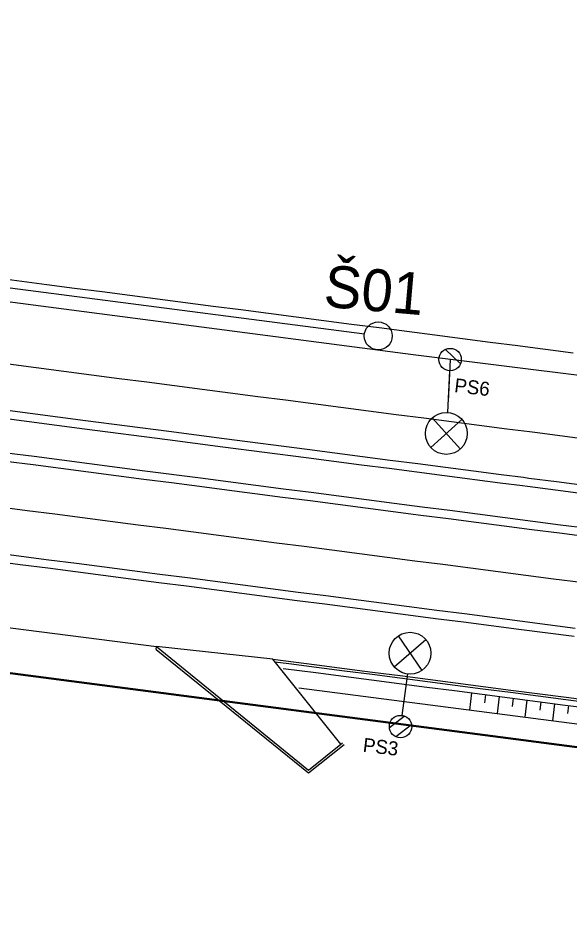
# Model space of a CAD drawing. Extents: x -669661 to -669105, y -977202 to -977030.
# Drawn here: x -669176.021 to -669175.034, y -977098.402 to -977096.811 of the extents above; entities that cross this region are included whole.
import ezdxf

# ---------------------------------------------------------------- set-up
doc = ezdxf.new("R2010")
doc.units = 0
doc.layers.add('Schéma', color=7, linetype='Continuous')

msp = doc.modelspace()

# ---------------------------------------------------------------- linework, layer by layer
at = {"layer": 'Schéma'}
for p, q in [((-669175.313, -977097.4136), (-669176.4676, -977097.2634)), ((-669175.2549, -977097.4042), (-669175.2293, -977097.4286)), ((-669174.42, -977097.5262), (-669175.313, -977097.4136)), ((-669175.2469, -977097.4222), (-669175.2507, -977097.4971)), ((-669176.0376, -977097.4301), (-669175.988, -977097.4366)), ((-669175.988, -977097.4366), (-669175.9384, -977097.443)), ((-669175.9384, -977097.443), (-669175.8889, -977097.4494)), ((-669175.2479, -977097.4422), (-669175.2517, -977097.5171)), ((-669175.8889, -977097.4494), (-669175.8393, -977097.4559)), ((-669175.8393, -977097.4559), (-669175.7897, -977097.4623)), ((-669175.7897, -977097.4623), (-669175.7401, -977097.4687)), ((-669175.7401, -977097.4687), (-669175.6905, -977097.4752)), ((-669175.6905, -977097.4752), (-669175.6409, -977097.4816)), ((-669175.6409, -977097.4816), (-669175.5913, -977097.4881)), ((-669175.5913, -977097.4881), (-669175.5418, -977097.4945)), ((-669175.5418, -977097.4945), (-669175.4922, -977097.5009)), ((-669175.4922, -977097.5009), (-669175.4426, -977097.5074)), ((-669175.4426, -977097.5074), (-669175.393, -977097.5138)), ((-669175.393, -977097.5138), (-669175.3434, -977097.5203)), ((-669175.3434, -977097.5203), (-669175.2938, -977097.5267)), ((-669175.2938, -977097.5267), (-669175.2443, -977097.5331)), ((-669175.2258, -977097.5294), (-669175.2815, -977097.5797)), ((-669175.2788, -977097.5267), (-669175.2286, -977097.5824)), ((-669175.2443, -977097.5331), (-669175.1947, -977097.5396)), ((-669175.1947, -977097.5396), (-669175.1451, -977097.546)), ((-669175.1451, -977097.546), (-669175.105, -977097.5512)), ((-669175.105, -977097.5512), (-669175.0955, -977097.5524)), ((-669175.0955, -977097.5524), (-669175.0459, -977097.5589)), ((-669175.0459, -977097.5589), (-669174.9963, -977097.5653)), ((-669175.2556, -977097.592), (-669175.2556, -977097.592)), ((-669176.0535, -977097.6857), (-669176.004, -977097.6921)), ((-669176.004, -977097.6921), (-669175.9544, -977097.6986)), ((-669175.9544, -977097.6986), (-669175.9048, -977097.705)), ((-669175.9048, -977097.705), (-669175.8552, -977097.7114)), ((-669175.8552, -977097.7114), (-669175.8056, -977097.7179)), ((-669175.8056, -977097.7179), (-669175.756, -977097.7243)), ((-669175.756, -977097.7243), (-669175.7065, -977097.7308)), ((-669175.7065, -977097.7308), (-669175.6569, -977097.7372)), ((-669175.6569, -977097.7372), (-669175.6073, -977097.7436)), ((-669175.6073, -977097.7436), (-669175.5577, -977097.7501)), ((-669175.5577, -977097.7501), (-669175.5081, -977097.7565)), ((-669175.5081, -977097.7565), (-669175.4585, -977097.7629)), ((-669175.4585, -977097.7629), (-669175.409, -977097.7694)), ((-669175.409, -977097.7694), (-669175.3594, -977097.7758)), ((-669175.3594, -977097.7758), (-669175.3098, -977097.7823)), ((-669175.3098, -977097.7823), (-669175.2602, -977097.7887)), ((-669175.2602, -977097.7887), (-669175.2106, -977097.7951)), ((-669175.2106, -977097.7951), (-669175.161, -977097.8016)), ((-669175.161, -977097.8016), (-669175.1115, -977097.808)), ((-669175.1115, -977097.808), (-669175.0619, -977097.8145)), ((-669175.0619, -977097.8145), (-669175.0123, -977097.8209)), ((-669176.487, -977097.8445), (-669175.7727, -977097.9361)), ((-669176.5596, -977097.9156), (-669172.9388, -977098.388)), ((-669172.9388, -977098.388), (-669176.5333, -977097.9176)), ((-669172.9388, -977098.388), (-669176.5333, -977097.9176)), ((-669172.8431, -977098.4024), (-669176.5328, -977097.9177)), ((-669175.3399, -977097.917), (-669175.2973, -977097.9786)), ((-669175.7732, -977097.9409), (-669175.7727, -977097.9361)), ((-669175.7727, -977097.9361), (-669175.5004, -977098.157)), ((-669175.5641, -977097.9585), (-669175.7727, -977097.9361)), ((-669175.347, -977097.9721), (-669175.2902, -977097.9234)), ((-669175.7732, -977097.9409), (-669175.5004, -977098.1621)), ((-669175.4425, -977098.1107), (-669175.5641, -977097.9585)), ((-669175.3234, -977097.9849), (-669175.3331, -977098.0592)), ((-669175.5178, -977098.01), (-669174.6539, -977098.1217)), ((-669175.2119, -977098.0495), (-669175.2079, -977098.0188)), ((-669175.185, -977098.0366), (-669175.1832, -977098.0221)), ((-669175.1623, -977098.0559), (-669175.1584, -977098.0253)), ((-669175.1355, -977098.0431), (-669175.1336, -977098.0285)), ((-669175.1128, -977098.0624), (-669175.1088, -977098.0317)), ((-669175.0859, -977098.0495), (-669175.084, -977098.0349)), ((-669175.0632, -977098.0688), (-669175.0592, -977098.0382)), ((-669175.0363, -977098.0559), (-669175.0344, -977098.0414)), ((-669175.3555, -977098.0805), (-669175.3292, -977098.0603)), ((-669175.3441, -977098.097), (-669175.3161, -977098.0754)), ((-669175.5004, -977098.157), (-669175.4393, -977098.1082)), ((-669175.5004, -977098.1621), (-669175.4368, -977098.1113))]:
    msp.add_line(p, q, dxfattribs=at)
for points in [[(-669175.4004, -977097.3767), (-669178.3011, -977097.0001), (-669179.1249, -977096.8105)], [(-669176.0679, -977097.2749), (-669175.9687, -977097.2878), (-669175.9191, -977097.2942), (-669175.8695, -977097.3007), (-669175.82, -977097.3071), (-669175.6712, -977097.3264), (-669175.6216, -977097.3329), (-669175.572, -977097.3393), (-669175.4233, -977097.3586), (-669175.3737, -977097.3651), (-669175.3241, -977097.3715), (-669175.2745, -977097.3779), (-669175.2249, -977097.3844), (-669175.1754, -977097.3908), (-669175.1258, -977097.3973), (-669175.0857, -977097.4025), (-669175.0762, -977097.4037), (-669175.0266, -977097.4101)], [(-669176.4757, -977097.4716), (-669176.3972, -977097.4817), (-669176.3477, -977097.4882), (-669176.2981, -977097.4946), (-669176.1493, -977097.5139), (-669176.0502, -977097.5268), (-669176.0006, -977097.5332), (-669175.951, -977097.5397), (-669175.9014, -977097.5461), (-669175.7527, -977097.5654), (-669175.7031, -977097.5719), (-669175.6535, -977097.5783), (-669175.5047, -977097.5976), (-669175.4552, -977097.6041), (-669175.4056, -977097.6105), (-669175.356, -977097.6169), (-669175.3064, -977097.6234), (-669175.2568, -977097.6298), (-669175.1576, -977097.6427), (-669175.1176, -977097.6479), (-669175.1081, -977097.6491), (-669175.0585, -977097.6556), (-669175.0089, -977097.662)], [(-669176.0482, -977097.5119), (-669175.9986, -977097.5184), (-669175.9491, -977097.5248), (-669175.8995, -977097.5312), (-669175.7507, -977097.5506), (-669175.7011, -977097.557), (-669175.6516, -977097.5634), (-669175.5028, -977097.5828), (-669175.4532, -977097.5892), (-669175.4036, -977097.5956), (-669175.3541, -977097.6021), (-669175.3045, -977097.6085), (-669175.2549, -977097.6149), (-669175.2053, -977097.6214), (-669175.1557, -977097.6278), (-669175.1157, -977097.633), (-669175.1061, -977097.6343), (-669175.0566, -977097.6407), (-669175.007, -977097.6471)], [(-669176.4835, -977097.5315), (-669176.1897, -977097.5697), (-669176.1402, -977097.5761), (-669176.0906, -977097.5826), (-669176.041, -977097.589), (-669175.9914, -977097.5954), (-669175.9418, -977097.6019), (-669175.8922, -977097.6083), (-669175.8427, -977097.6148), (-669175.7931, -977097.6212), (-669175.6939, -977097.6341), (-669175.6443, -977097.6405), (-669175.5947, -977097.6469), (-669175.5452, -977097.6534), (-669175.4956, -977097.6598), (-669175.446, -977097.6663), (-669175.3468, -977097.6791), (-669175.2972, -977097.6856), (-669175.2477, -977097.692), (-669175.1981, -977097.6985), (-669175.0989, -977097.7113), (-669175.0493, -977097.7178), (-669174.9997, -977097.7242)], [(-669176.0429, -977097.6039), (-669175.9933, -977097.6103), (-669175.9438, -977097.6168), (-669175.8942, -977097.6232), (-669175.8446, -977097.6296), (-669175.795, -977097.6361), (-669175.7454, -977097.6425), (-669175.6958, -977097.6489), (-669175.6463, -977097.6554), (-669175.5967, -977097.6618), (-669175.5471, -977097.6683), (-669175.4975, -977097.6747), (-669175.4479, -977097.6811), (-669175.3983, -977097.6876), (-669175.3488, -977097.694), (-669175.2992, -977097.7005), (-669175.2496, -977097.7069), (-669175.2, -977097.7133), (-669175.1504, -977097.7198), (-669175.1008, -977097.7262), (-669175.0513, -977097.7326), (-669175.0017, -977097.7391)], [(-669176.0642, -977097.7675), (-669176.0146, -977097.7739), (-669175.965, -977097.7804), (-669175.9154, -977097.7868), (-669175.8658, -977097.7933), (-669175.8163, -977097.7997), (-669175.7667, -977097.8061), (-669175.7171, -977097.8126), (-669175.6675, -977097.819), (-669175.6179, -977097.8254), (-669175.5683, -977097.8319), (-669175.5188, -977097.8383), (-669175.4692, -977097.8448), (-669175.4196, -977097.8512), (-669175.37, -977097.8576), (-669175.3204, -977097.8641), (-669175.2708, -977097.8705), (-669175.2212, -977097.877), (-669175.1717, -977097.8834), (-669175.1221, -977097.8898), (-669175.0725, -977097.8963), (-669175.0229, -977097.9027)], [(-669176.0661, -977097.7824), (-669176.0165, -977097.7888), (-669175.9669, -977097.7953), (-669175.9174, -977097.8017), (-669175.8678, -977097.8081), (-669175.8182, -977097.8146), (-669175.7686, -977097.821), (-669175.719, -977097.8274), (-669175.5703, -977097.8468), (-669175.5207, -977097.8532), (-669175.4711, -977097.8596), (-669175.4215, -977097.8661), (-669175.3719, -977097.8725), (-669175.3223, -977097.879), (-669175.2728, -977097.8854), (-669175.2232, -977097.8918), (-669175.1736, -977097.8983), (-669175.124, -977097.9047), (-669175.0248, -977097.9176)], [(-669175.5641, -977097.9585), (-669175.4853, -977097.9687), (-669175.4357, -977097.9752), (-669175.3861, -977097.9816), (-669175.3365, -977097.988), (-669175.2869, -977097.9945), (-669175.2373, -977098.0009), (-669175.1878, -977098.0074), (-669175.1382, -977098.0138), (-669175.039, -977098.0267), (-669174.9894, -977098.0331), (-669174.9398, -977098.0395), (-669174.8903, -977098.046), (-669174.8407, -977098.0524), (-669174.7911, -977098.0589), (-669174.7746, -977098.061), (-669174.7415, -977098.0653), (-669174.6919, -977098.0717), (-669174.6423, -977098.0782), (-669174.589, -977098.0851)], [(-669175.5605, -977097.963), (-669175.5354, -977097.9663), (-669175.4858, -977097.9727), (-669175.4362, -977097.9791), (-669175.3866, -977097.9856), (-669175.337, -977097.992), (-669175.2874, -977097.9984), (-669175.2379, -977098.0049), (-669175.1883, -977098.0113), (-669175.1387, -977098.0178), (-669175.0395, -977098.0306), (-669174.9899, -977098.0371), (-669174.9404, -977098.0435), (-669174.8908, -977098.0499), (-669174.7916, -977098.0628), (-669174.7751, -977098.065), (-669174.742, -977098.0693), (-669174.6924, -977098.0757), (-669174.6429, -977098.0821), (-669174.5855, -977098.0896)], [(-669175.5458, -977097.975), (-669175.4871, -977097.9826), (-669175.4375, -977097.989), (-669175.3879, -977097.9955), (-669175.3383, -977098.0019), (-669175.2887, -977098.0084), (-669175.2391, -977098.0148), (-669175.1896, -977098.0212), (-669175.14, -977098.0277), (-669175.0408, -977098.0406), (-669174.9912, -977098.047), (-669174.9416, -977098.0534), (-669174.8921, -977098.0599), (-669174.7929, -977098.0727), (-669174.7764, -977098.0749), (-669174.7433, -977098.0792), (-669174.6937, -977098.0856), (-669174.6441, -977098.0921), (-669174.5769, -977098.1008)]]:
    msp.add_lwpolyline(points, dxfattribs=at)
for centre, radius in [((-669175.3756, -977097.3799), 0.025), ((-669175.2469, -977097.4222), 0.02), ((-669175.2537, -977097.5545), 0.0375), ((-669175.3186, -977097.9478), 0.0374), ((-669175.3357, -977098.0791), 0.02)]:
    msp.add_circle(centre, radius, dxfattribs=at)

# ---------------------------------------------------------------- texts
for s, height, rotation, p in [('Š01', 0.075, 354.9976, (-669175.4749, -977097.3273)), ('PS6', 0.025, 353.1527, (-669175.2403, -977097.4803)), ('PS3', 0.025, 353.1527, (-669175.404, -977098.124))]:
    msp.add_text(s, height=height, rotation=rotation, dxfattribs=at).set_placement(p)

doc.saveas('drawing.dxf')
